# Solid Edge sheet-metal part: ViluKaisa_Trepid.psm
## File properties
Author: kaisa
Template: Iso Metric Sheet Metal.psm
Last saved by: kaisa
Revision: 1
Application: Solid Edge
Accuracy: 0.990
Material Thickness: 1.00 mm
Bend Radius: 1.00 mm
Relief Width: 1.00 mm
Relief Length: 0.00 mm
Neutral Factor: 0.330
Minimum Arc Length: 0.10 mm
Deviational Tolerance: 0.10 mm
Username: kaisa
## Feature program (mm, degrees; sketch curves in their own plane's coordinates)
base tab "unnamed BaseTab 1"
jog tab "JogTab_1"  OffsetDistance = 10 mm
jog tab "JogTab_3"  OffsetDistance = 10 mm
jog tab "JogTab_4"  OffsetDistance = 10 mm
jog tab "JogTab_5"  OffsetDistance = 10 mm
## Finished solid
Body 1: solid body, 38 faces, 108 edges, 72 vertices.
  Faces by surface: plane 22, cylinder 16
  Edges by curve: line 76, circle 32
Bounding box of the edges (mm): 30.000 x 35.304 x 45.000, from (-15, -5.3038, 0) to (15, 30, 45).
Cylindrical faces by radius (mm): R1 x8, R2 x8
Planar faces by outward normal: +x 1, +y 5, +z 5, -x 1, -y 5, -z 5
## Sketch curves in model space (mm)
line (3.6892, 2.1039, 1) -> (-3.6892, 2.1039, 1)
line (4.3651, 10.1864, 1) -> (-4.0271, 10.1864, 1)
line (4.703, 17.4523, 1) -> (-3.8018, 17.4523, 1)
line (5.1244, 25, 1) -> (-4.0368, 25, 1)
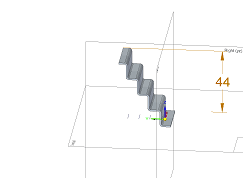
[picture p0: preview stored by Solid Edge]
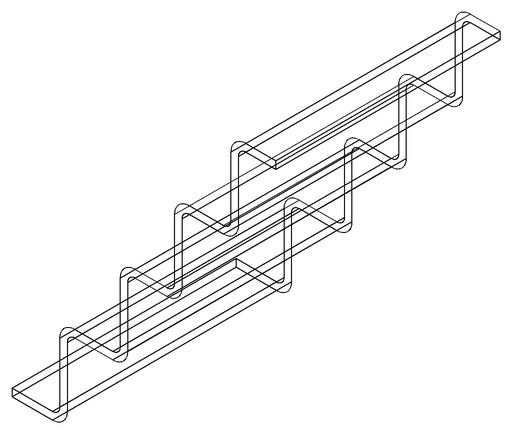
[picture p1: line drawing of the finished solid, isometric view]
